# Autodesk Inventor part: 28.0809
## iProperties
Created: 2009-01
Part Number: 28.0809
Document SubType Name: Modeling
Designer: Administrator
Density: 2.71 g/cm^3
Material: Aluminum-6061
Mass: 34.5471 g
Surface Area: 46.8656 cm^2
Volume: 12.748 cm^3
Description: SHAFT RETENTION DEVICE LEFT LR 16
Author: Administrator
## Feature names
1. Base1
